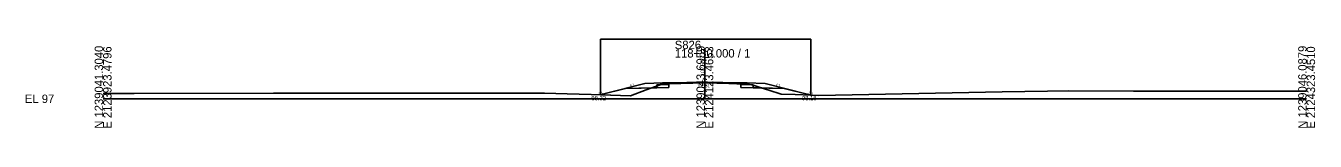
# Model space of a CAD drawing. Extents: x 2119282 to 2119710, y 1215030 to 1220057.
# Drawn here: x 2119281.9 to 2119710.4, y 1217030.1 to 1217059.7 of the extents above; entities that cross this region are included whole.
import ezdxf

# ---------------------------------------------------------------- set-up
doc = ezdxf.new("R2010")
doc.units = 0
for name, color, linetype in [('XS_CELL', 7, 'Continuous'), ('XS_M_DITCH', 7, 'Continuous'), ('XS_M_SHAPES_EARTHWORK', 7, 'Continuous'), ('XS_P_FINISHED_GRADE', 7, 'Continuous'), ('XS_P_FINISHED_GRADE_ELEV_TX', 7, 'Continuous'), ('XS_P_SUBGRADE_GRANULAR', 7, 'Continuous'), ('XS_P_SUBGRADE_PAVEMENT', 7, 'Continuous'), ('XS_P_TX_DCH', 7, 'Continuous'), ('XS_P_TX_FS_BS', 7, 'Continuous'), ('XS_X_GROUND', 7, 'Continuous'), ('XS_X_GROUND_TX', 7, 'Continuous')]:
    doc.layers.add(name, color=color, linetype=linetype)

msp = doc.modelspace()

# ---------------------------------------------------------------- linework, layer by layer
at = {"layer": 'XS_CELL'}
for p, q in [((2119507.6, 1217039.8), (2119507.6, 1217056.36)), ((2119307.6, 1217039.8), (2119507.6, 1217039.8)), ((2119507.6, 1217039.8), (2119707.6, 1217039.8))]:
    msp.add_line(p, q, dxfattribs=at)
at = {"layer": 'XS_M_DITCH'}
for p, q in [((2119472.87, 1217041.13), (2119472.87, 1217059.68)), ((2119472.87, 1217059.68), (2119542.77, 1217059.68)), ((2119542.77, 1217040.98), (2119542.77, 1217059.68))]:
    msp.add_line(p, q, dxfattribs=at)
at = {"layer": 'XS_M_SHAPES_EARTHWORK'}
for p, q in [((2119473.6, 1217041.37), (2119472.87, 1217041.13)), ((2119481.24, 1217043.28), (2119473.6, 1217041.37)), ((2119489.95, 1217043.46), (2119481.24, 1217043.28)), ((2119482.91, 1217040.76), (2119488.07, 1217042.78)), ((2119488.07, 1217042.78), (2119489.95, 1217043.46)), ((2119491.6, 1217044.05), (2119489.95, 1217043.46)), ((2119489.95, 1217043.46), (2119491.6, 1217043.49)), ((2119492.88, 1217044.51), (2119491.6, 1217044.05)), ((2119491.6, 1217044.05), (2119491.6, 1217043.49)), ((2119491.6, 1217043.49), (2119491.6, 1217044.05)), ((2119491.6, 1217043.49), (2119495.6, 1217043.57)), ((2119492.95, 1217044.52), (2119492.88, 1217044.51)), ((2119492.95, 1217044.52), (2119495.6, 1217044.57)), ((2119495.6, 1217044.57), (2119492.95, 1217044.52)), ((2119492.97, 1217044.54), (2119492.95, 1217044.52)), ((2119493.96, 1217044.9), (2119492.97, 1217044.54)), ((2119495.6, 1217045.03), (2119493.96, 1217044.9)), ((2119495.6, 1217043.57), (2119495.6, 1217044.57)), ((2119520.27, 1217044.72), (2119519.6, 1217044.75)), ((2119519.6, 1217044.75), (2119519.6, 1217044.57)), ((2119522.26, 1217044.52), (2119519.6, 1217044.57)), ((2119519.6, 1217044.57), (2119519.6, 1217043.57)), ((2119519.6, 1217044.57), (2119522.26, 1217044.52)), ((2119519.6, 1217043.57), (2119523.6, 1217043.49)), ((2119522.25, 1217044.52), (2119520.27, 1217044.72)), ((2119522.26, 1217044.52), (2119522.25, 1217044.52)), ((2119522.38, 1217044.51), (2119522.26, 1217044.52)), ((2119523.16, 1217044.44), (2119522.38, 1217044.51)), ((2119523.6, 1217044.29), (2119523.16, 1217044.44)), ((2119523.6, 1217043.49), (2119523.6, 1217044.29)), ((2119523.6, 1217044.29), (2119523.6, 1217043.49)), ((2119526.29, 1217043.44), (2119523.6, 1217044.29)), ((2119523.6, 1217043.49), (2119526.29, 1217043.44)), ((2119533.97, 1217043.28), (2119526.29, 1217043.44)), ((2119526.29, 1217043.44), (2119528.81, 1217042.63)), ((2119528.81, 1217042.63), (2119532.91, 1217041.39)), ((2119532.91, 1217041.39), (2119537.58, 1217041.21)), ((2119541.6, 1217041.37), (2119533.97, 1217043.28)), ((2119537.58, 1217041.21), (2119542.77, 1217040.98)), ((2119542.77, 1217040.98), (2119541.6, 1217041.37)), ((2119472.87, 1217041.13), (2119482.91, 1217040.76))]:
    msp.add_line(p, q, dxfattribs=at)
msp.add_lwpolyline([(2119495.6, 1217044.57), (2119495.6, 1217044.82), (2119495.6, 1217045.03)], dxfattribs=at)
at = {"layer": 'XS_P_FINISHED_GRADE'}
for p, q in [((2119473.6, 1217041.37), (2119472.87, 1217041.13)), ((2119487.6, 1217044.87), (2119473.6, 1217041.37)), ((2119493.6, 1217045.11), (2119487.6, 1217044.87)), ((2119495.6, 1217045.15), (2119493.6, 1217045.11)), ((2119507.6, 1217045.39), (2119495.6, 1217045.15)), ((2119507.6, 1217045.39), (2119519.6, 1217045.15)), ((2119519.6, 1217045.15), (2119521.6, 1217045.11)), ((2119521.6, 1217045.11), (2119527.6, 1217044.87)), ((2119527.6, 1217044.87), (2119541.6, 1217041.37)), ((2119541.6, 1217041.37), (2119542.77, 1217040.98))]:
    msp.add_line(p, q, dxfattribs=at)
at = {"layer": 'XS_P_SUBGRADE_GRANULAR'}
for p, q in [((2119491.6, 1217043.49), (2119481.24, 1217043.28)), ((2119492.95, 1217044.52), (2119491.6, 1217044.46)), ((2119491.6, 1217043.49), (2119491.6, 1217044.46)), ((2119495.6, 1217043.57), (2119491.6, 1217043.49)), ((2119495.6, 1217043.57), (2119495.61, 1217044.57)), ((2119519.6, 1217043.57), (2119519.59, 1217044.57)), ((2119519.6, 1217043.57), (2119523.6, 1217043.49)), ((2119522.26, 1217044.52), (2119523.6, 1217044.46)), ((2119523.6, 1217043.49), (2119523.6, 1217044.46)), ((2119523.6, 1217043.49), (2119533.97, 1217043.28))]:
    msp.add_line(p, q, dxfattribs=at)
at = {"layer": 'XS_P_SUBGRADE_PAVEMENT'}
for p, q in [((2119493.1, 1217044.77), (2119492.95, 1217044.52)), ((2119495.61, 1217044.57), (2119492.95, 1217044.52)), ((2119493.6, 1217045.11), (2119493.1, 1217044.77)), ((2119507.6, 1217045.06), (2119495.61, 1217044.82)), ((2119495.61, 1217044.57), (2119495.61, 1217044.82)), ((2119507.6, 1217045.06), (2119519.6, 1217044.82)), ((2119519.59, 1217044.57), (2119519.6, 1217044.82)), ((2119519.59, 1217044.57), (2119522.26, 1217044.52)), ((2119521.6, 1217045.11), (2119522.11, 1217044.77)), ((2119522.11, 1217044.77), (2119522.26, 1217044.52))]:
    msp.add_line(p, q, dxfattribs=at)
at = {"layer": 'XS_X_GROUND'}
for p, q in [((2119307.6, 1217041.57), (2119317.98, 1217041.6)), ((2119317.98, 1217041.6), (2119364.19, 1217041.64)), ((2119364.19, 1217041.64), (2119410.07, 1217041.64)), ((2119410.07, 1217041.64), (2119454.34, 1217041.72)), ((2119454.34, 1217041.72), (2119461.78, 1217041.44)), ((2119461.78, 1217041.44), (2119469.79, 1217041.24)), ((2119469.79, 1217041.24), (2119482.91, 1217040.76)), ((2119482.91, 1217040.76), (2119488.07, 1217042.78)), ((2119488.07, 1217042.78), (2119493.96, 1217044.9)), ((2119493.96, 1217044.9), (2119496.66, 1217045.12)), ((2119496.66, 1217045.12), (2119498.93, 1217045.16)), ((2119498.93, 1217045.16), (2119507.6, 1217045.31)), ((2119507.6, 1217045.31), (2119508.36, 1217045.32)), ((2119508.36, 1217045.32), (2119520.27, 1217044.72)), ((2119520.27, 1217044.72), (2119523.16, 1217044.44)), ((2119523.16, 1217044.44), (2119528.81, 1217042.63)), ((2119528.81, 1217042.63), (2119532.91, 1217041.39)), ((2119532.91, 1217041.39), (2119537.58, 1217041.21)), ((2119537.58, 1217041.21), (2119545.48, 1217040.86)), ((2119545.48, 1217040.86), (2119606.45, 1217042.09)), ((2119606.45, 1217042.09), (2119621.43, 1217042.39)), ((2119621.43, 1217042.39), (2119628.3, 1217042.4)), ((2119628.3, 1217042.4), (2119650.07, 1217042.38)), ((2119650.07, 1217042.38), (2119707.6, 1217042.38))]:
    msp.add_line(p, q, dxfattribs=at)

# ---------------------------------------------------------------- texts
at = {"layer": 'XS_CELL'}
for s, p in [('S826', (2119497.6, 1217056.36)), ('118+50.000 / 1', (2119497.6, 1217053.56)), ('EL 97', (2119281.6, 1217038.4))]:
    msp.add_text(s, height=2.8, dxfattribs=at).set_placement(p)
for s, p in [('N 1239041.3040', (2119307.6, 1217029.8)), ('E 2123923.4796', (2119310.4, 1217029.8)), ('N 1239043.6959', (2119507.6, 1217029.8)), ('E 2124123.4653', (2119510.4, 1217029.8)), ('N 1239046.0879', (2119707.6, 1217029.8)), ('E 2124323.4510', (2119710.4, 1217029.8))]:
    msp.add_text(s, height=2.8, rotation=90, dxfattribs=at).set_placement(p)
at = {"layer": 'XS_P_FINISHED_GRADE_ELEV_TX'}
msp.add_text('102.59', height=1.25, rotation=90, dxfattribs=at).set_placement((2119507.45, 1217047.47))
at = {"layer": 'XS_P_TX_DCH'}
for s, p in [('98.32', (2119469.89, 1217039.3)), ('98.18', (2119539.87, 1217039.3))]:
    msp.add_text(s, height=1.4, dxfattribs=at).set_placement(p)
at = {"layer": 'XS_P_TX_FS_BS'}
for s, rotation, p in [('3:1', 18.4349, (2119472.34, 1217041.02)), ('4:1', 14.0362, (2119482.77, 1217043.84)), ('4:1', 345.9638, (2119531.11, 1217044.17)), ('3:1', 341.5651, (2119542.02, 1217041.45))]:
    msp.add_text(s, height=0.8, rotation=rotation, dxfattribs=at).set_placement(p)
at = {"layer": 'XS_X_GROUND_TX'}
msp.add_text('102.51', height=1, dxfattribs=at).set_placement((2119505.03, 1217043.61))

doc.saveas('drawing.dxf')
